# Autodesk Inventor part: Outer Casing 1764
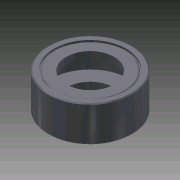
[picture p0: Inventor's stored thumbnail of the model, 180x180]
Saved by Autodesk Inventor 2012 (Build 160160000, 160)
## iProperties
Created: 2009-01
Part Number: Outer Casing 1764
Document SubType Name: Modeling
Designer: pmulligan
Density: 1 g/cm^3
Mass: 1.30143 g
Surface Area: 21.4282 cm^2
Volume: 1.30143 cm^3
Material: Default
Author: pmulligan
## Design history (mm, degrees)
sketch "Sketch1"
  geometry: L1 (-27.546, 4.227)-(-26.022, 4.227); L2 (-26.022, 4.227)-(-26.022, -5.247); L3 (-26.022, -5.247)-(-27.546, -5.247); L4 (-27.546, -5.247)-(-27.546, 4.227); L5 (-16.434, 9.028)-(-16.434, -15.355)
  constraints: 10 end point, 3 parallel, 1 horizontal, 1 perpendicular
  dimensions: "d0" = 9.4742 distance of L3.end L1.start; "d1" = 1.524 distance of L1.start L1.end; "d2" = 11.1125 distance between parallel lines of L5 L4
revolve "Revolution1" sketch "Sketch1" stored, may be unused: angle "d3" = 90 deg
workplane "Work Plane1"
sketch "Sketch2"
  geometry: C1 r 11.113 at (0, 0); C2 r 6.35 at (0, 0)
  constraints: 2 centre point, 1 coincident
  dimensions: "d5" = 12.7 diameter of C2; "d35" = 22.225 diameter of C1
extrude "Extrusion1" join sketch "Sketch2" distance "d6" = 1.92072; taper "d7" = 0 deg
workplane "Work Plane2"
sketch "Sketch3"
  geometry: C1 r 11.113 at (0, 0); C2 r 6.35 at (0, 0)
  constraints: 2 centre point, 1 coincident
  dimensions: "d9" = 12.7 diameter of C2; "d34" = 22.225 diameter of C1
extrude "Extrusion2" join sketch "Sketch3" distance "d10" = 1.92072; taper "d11" = 0 deg
workplane "Work Plane3"
sketch "Sketch4"
  geometry: C1 r 10.351 at (0, 0)
  constraints: 1 centre point
  dimensions: "d13" = 20.701 diameter of C1
extrude "Extrusion3" cut sketch "Sketch4" distance "d14" = 5.12475; taper "d15" = 0 deg
sketch "Sketch5"
  geometry: C1 r 9.589 at (0, 0) reference; C2 r 9.335 at (0, 0)
  constraints: 1 centre point, 1 coincident
  dimensions: "d16" = 0.254 radial gap between concentric circles of C1 C2
extrude "Extrusion4" cut sketch "Sketch5" distance "d17" = 0.254; taper "d18" = 0 deg
chamfer "Chamfer1" distance "d19" = 0.254; stored, may be unused: second distance "d20" = 3.175, angle "d21" = 45 deg
sketch "Sketch6"
  geometry: C1 r 9.589 at (0, 0) reference; C2 r 9.335 at (0, 0)
  constraints: 1 centre point, 1 coincident
  dimensions: "d22" = 0.254 radial gap between concentric circles of C1 C2
extrude "Extrusion5" cut sketch "Sketch6" distance "d23" = 0.254; taper "d24" = 0 deg
chamfer "Chamfer2" distance "d25" = 0.254; stored, may be unused: second distance "d26" = 3.175, angle "d27" = 45 deg
chamfer "Chamfer3" distance "d28" = 0.254; stored, may be unused: second distance "d29" = 3.175, angle "d30" = 45 deg
chamfer "Chamfer4" distance "d31" = 0.254; stored, may be unused: second distance "d32" = 3.175, angle "d33" = 45 deg
body "Solid1"
other parameters: "d4" = -0.254, "d8" = -0.254, "d12" = 0
